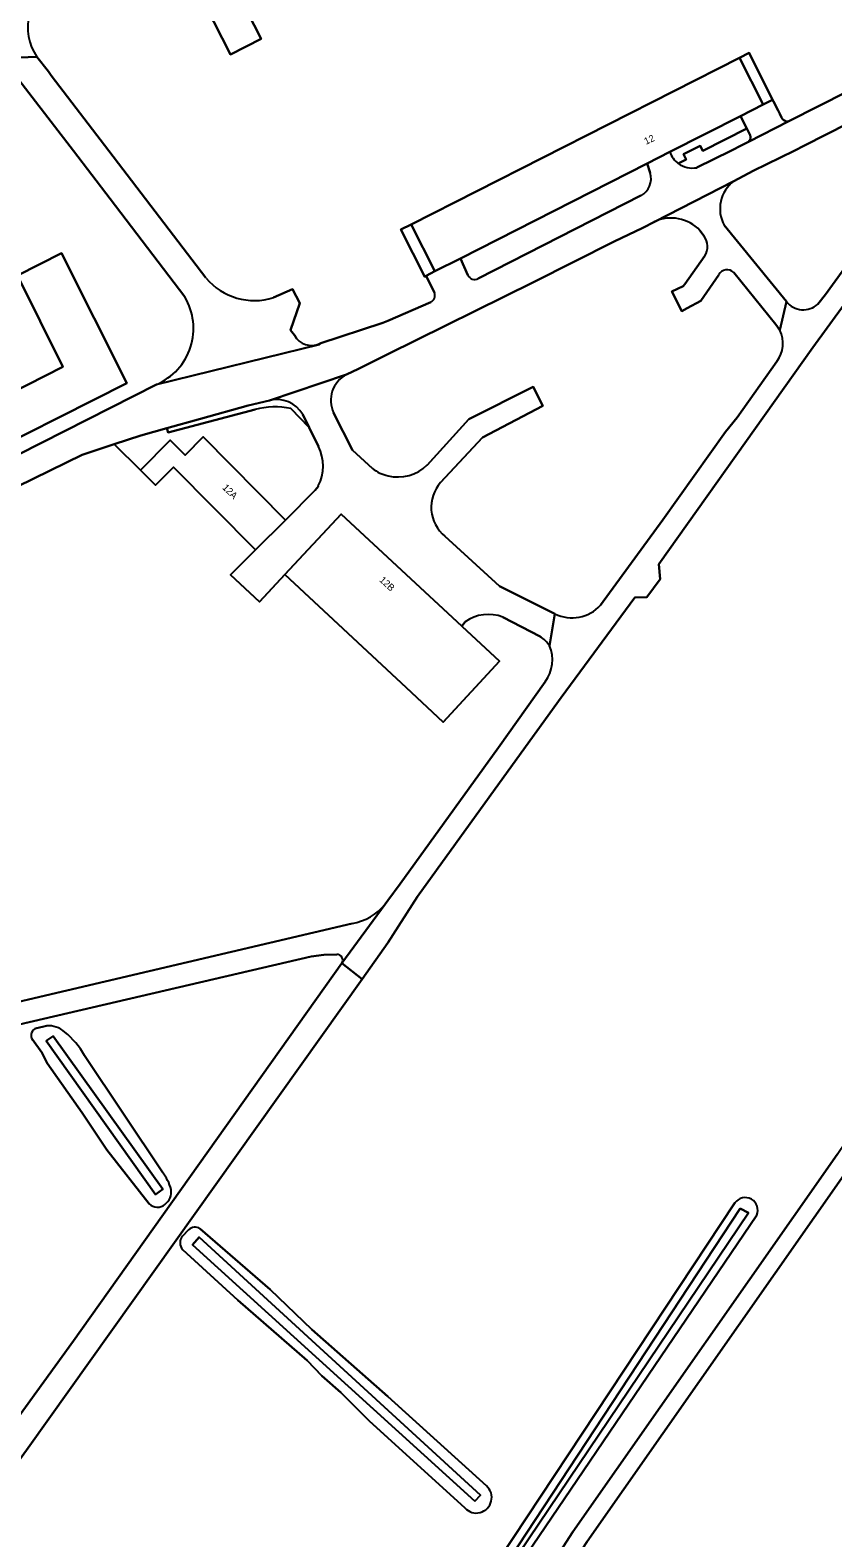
# Model space of a CAD drawing. Extents: x 158132 to 159664, y 385256 to 387218.
# Drawn here: x 158948 to 159064.7, y 386048.5 to 386267.5 of the extents above; entities that cross this region are included whole.
import ezdxf

# ---------------------------------------------------------------- set-up
doc = ezdxf.new("R2010")
doc.units = 0
for name, color, linetype in [('IMGEO_Gemengd_bos', 7, 'Continuous'), ('IMGEO_Grasland_overig', 7, 'Continuous'), ('IMGEO_Groenvoorziening', 7, 'Continuous'), ('IMGEO_Loofbos', 7, 'Continuous'), ('IMGEO_Oever', 7, 'Continuous'), ('IMGEO_Pand', 7, 'Continuous'), ('IMGEO_Pand_nummerreeks', 7, 'Continuous'), ('IMGEO_Rijbaan_lokaal_gesloten', 7, 'Continuous'), ('IMGEO_Rijbaan_lokaal_open', 7, 'Continuous'), ('IMGEO_Voetpad_open', 7, 'Continuous'), ('IMGEO_Waterloop', 7, 'Continuous')]:
    doc.layers.add(name, color=color, linetype=linetype)

msp = doc.modelspace()

# ---------------------------------------------------------------- linework, layer by layer
at = {"layer": 'IMGEO_Gemengd_bos'}
for points in [[(158987.13, 385983.76), (158985.38, 385985.66), (159024.58, 386045.84), (159026.86, 386049.34), (159065.31, 386104.15), (159074.76, 386118.24), (159086.39, 386135.58), (159115.48, 386177.93), (159137.05, 386210.07), (159143.29, 386219.37), (159143.28, 386220.9), (159143.27, 386223.44), (159126.17, 386240.76), (159117.05, 386250), (159112.16, 386254.95), (159110, 386256.99), (159100.09, 386266.87)], [(159081.8, 386262.26), (159076.17, 386258.72), (159060.54, 386250.75), (159059.02, 386250), (159053.08, 386247.07), (159050.25, 386245.6)], [(159062.49, 386227.7), (159063.57, 386229.11), (159071.86, 386240.54), (159078.66, 386250), (159082.37, 386255.16)], [(159048.86, 386239.16), (159057.91, 386228.09)], [(159066.31, 386227.68), (159061.77, 386221.39), (159039.38, 386189.93), (159039.57, 386187.77), (159037.64, 386185.15), (159035.87, 386185.08), (159025.16, 386170.55), (159017.45, 386159.91), (159004.28, 386141.65), (159000, 386134.9), (158996.27, 386129.66), (158947.71, 386061.54), (158903.24, 386000)], [(158980.75, 386192.01), (158968.81, 386204.04), (158966.21, 386201.42), (158964.03, 386203.58), (158960.21, 386207.36), (158955.54, 386205.8), (158946.13, 386201.24), (158935.08, 386195.64), (158931.48, 386193.8)], [(159011.21, 386181.56), (159010.72, 386180.94), (159010.8, 386180.87), (159016.23, 386175.82), (159008.04, 386167), (159002.62, 386172.04), (158985.01, 386188.42), (158981.32, 386184.47), (158977.11, 386188.39), (158980.75, 386192.01)], [(159022.1, 386179.43), (159016.7, 386182.23)], [(158999.61, 386140.55), (159000, 386141.08), (159001.77, 386143.48), (159016.07, 386163.32), (159022.83, 386172.86)], [(158802.75, 386092.98), (158804.95, 386093.18), (158994.79, 386137.73)], [(158797.66, 386086.29), (158812.86, 386069.29), (158886.2, 385981.64), (158898.44, 386000), (158954.3, 386077.08), (158993.31, 386131.95)], [(158992.55, 386133.23), (158990.7, 386133.19), (158988.86, 386132.94), (158847.34, 386100.03), (158802.76, 386090.03)], [(158948.94, 386122.53), (158950.37, 386122.86)], [(158965.3, 386097.01), (158959.16, 386104.84), (158955.56, 386110.22), (158950.46, 386117.42), (158949.67, 386119.01), (158948.31, 386120.86)], [(158955.91, 386118.57), (158967.22, 386101.61)], [(158975.96, 385985.89), (158985.64, 386000), (159000, 386020.95), (159050.43, 386097.13)], [(159053.59, 386095.36), (159021.93, 386048.68), (159014.34, 386037.49), (159000, 386016.65), (158988.53, 386000), (158981.53, 385989.84), (158977.92, 385984.59)], [(158970.12, 386092.32), (158971, 386093.21)], [(158972.7, 386093.39), (158982.89, 386084.58), (158988.94, 386078.73), (159000, 386069), (159014.32, 386056.02)], [(159000, 386063), (158997.26, 386065.5), (158993.13, 386069.59), (158990.37, 386072), (158988.25, 386074.23), (158978.2, 386083.01), (158970.18, 386090.33)], [(159011.17, 386052.84), (159000, 386063)]]:
    msp.add_lwpolyline(points, dxfattribs=at)
for centre, radius, start, end in [((159053.34, 386241.56), 5.08, 127.4877, 208.1683), ((159060.38, 386230.04), 3.15, 218.2687, 312.0282), ((159014.57, 386176.89), 5.75, 68.2733, 125.7069), ((159019.72, 386175.62), 4.49, 33.3189, 58.0708), ((159018.62, 386176.03), 5.27, 323.0521, 22.9275), ((158993.43, 386145.57), 7.96, 279.819, 320.8727), ((158992.59, 386132.39), 0.844, 328.6516, 92.4979), ((158949.21, 386121.47), 1.09, 104.3488, 214.4042), ((158950.66, 386119.32), 3.55, 47.9229, 94.7052), ((158944.6, 386111.9), 13.13, 30.5542, 50.0095), ((158961.61, 386097.25), 7.11, 15.0151, 37.897), ((158966.29, 386098.73), 2.21, 305.4591, 9.459), ((158966.49, 386098.22), 1.7, 225.6124, 310.0133), ((159051.93, 386096.09), 1.82, 336.2967, 145.1548), ((158971.29, 386091.36), 1.51, 140.3052, 222.8547), ((158971.96, 386092.25), 1.36, 57.1738, 135.1287), ((159012.84, 386054.33), 2.24, 221.8777, 48.7556)]:
    msp.add_arc(centre, radius, start, end, dxfattribs=at)
at = {"layer": 'IMGEO_Grasland_overig'}
msp.add_lwpolyline([(159026.34, 386043.95), (159128.6, 385934.11), (159167.77, 385991.84), (159128.38, 386026.44), (159093.47, 386056.67), (159083.99, 386064.99), (159082.8, 386066.54), (159079.43, 386071.09), (159075.57, 386078.05), (159073.99, 386082.33), (159070.33, 386093.52), (159067.29, 386102.62), (159028.94, 386047.93)], close=True, dxfattribs=at)
at = {"layer": 'IMGEO_Groenvoorziening'}
for points in [[(159052.15, 386253.22), (159051.23, 386255.04), (159040.95, 386249.82)], [(159042.19, 386248.16), (159043.32, 386248.74), (159042.94, 386249.48), (159045.38, 386250.72), (159045.76, 386249.98), (159052.15, 386253.22)], [(159038.12, 386246.77), (159037.69, 386248.16), (159010.52, 386234.36), (159011.61, 386231.91)], [(159013.1, 386231.42), (159036.76, 386243.47)]]:
    msp.add_lwpolyline(points, dxfattribs=at)
for centre, radius, start, end in [((159044.27, 386251.01), 3.53, 199.7639, 233.8206), ((159035.43, 386245.94), 2.81, 298.175, 17.0175), ((159012.59, 386232.37), 1.08, 205.2305, 298.594)]:
    msp.add_arc(centre, radius, start, end, dxfattribs=at)
at = {"layer": 'IMGEO_Loofbos'}
for points in [[(159000.7, 386299.06), (158999.99, 386298.66), (158970.44, 386283.97), (158972.59, 386279.64), (158974.3, 386280.51), (158981.55, 386266.24), (158977.09, 386263.98), (158969.84, 386278.24), (158970.61, 386278.64), (158968.45, 386282.98)], [(158954.27, 386250), (158947.82, 386258.43), (158943.93, 386263.45)], [(158948.98, 386263.64), (158950.64, 386261.53), (158951.07, 386260.95), (158959.43, 386250), (158973.55, 386231.51)], [(159006.76, 386229.34), (159005.55, 386231.81), (159005.35, 386231.7), (159001.85, 386238.53), (159003.38, 386239.27), (159051.07, 386263.49), (159052.5, 386264.22), (159055.9, 386257.41), (159056.16, 386256.9), (159056.43, 386256.38), (159056.69, 386255.86), (159056.95, 386255.34), (159057.21, 386254.82), (159057.4, 386254.54), (159057.55, 386254.42), (159057.71, 386254.32), (159057.88, 386254.26), (159058.06, 386254.25), (159058.25, 386254.27), (159075.22, 386262.87)], [(158970.47, 386228.75), (158959.62, 386243.01), (158954.27, 386250)], [(159038.72, 386239.68), (159037.05, 386238.82), (159032.87, 386236.83), (159021.13, 386230.92), (159000, 386220.45), (158995.7, 386218.32), (158993.99, 386217.49)], [(159045.97, 386237.6), (159045.35, 386238.4)], [(159048.08, 386231.99), (159045.49, 386228.19), (159043.49, 386227.13), (159042.71, 386226.68), (159041.26, 386229.54), (159042.89, 386230.31), (159043.16, 386230.59), (159046.06, 386234.72)], [(159056.96, 386223.92), (159056.37, 386224.76), (159050.26, 386232.3)], [(158983.36, 386228.66), (158986.13, 386229.87), (158987.21, 386227.87), (158985.83, 386223.92), (158986.41, 386223.18)], [(158990.08, 386221.99), (158999.26, 386224.98), (159000, 386225.3), (159006.22, 386228.01)], [(159030.9, 386183.96), (159039.93, 386196.38), (159049.07, 386209.14), (159050.73, 386211.25), (159056.52, 386219.38)], [(158894.13, 386179.46), (158912.8, 386188.92), (158966.37, 386216.04)], [(159005.7, 386204.34), (159011.75, 386210.98), (159021.12, 386215.7), (159022.52, 386212.92), (159013.74, 386208.36), (159007.62, 386201.79)], [(158992.1, 386211.91), (158994.84, 386206.51), (158997.75, 386203.82)], [(159008.27, 386193.99), (159016.2, 386186.75), (159024.27, 386182.72)]]:
    msp.add_lwpolyline(points, dxfattribs=at)
msp.add_lwpolyline([(158952.56, 386235.1), (158962.03, 386216.21), (158937.65, 386203.93), (158934.84, 386209.51), (158952.76, 386218.61), (158946.17, 386231.87)], close=True, dxfattribs=at)
for centre, radius, start, end in [((158955.21, 386267.94), 7.57, 117.3529, 214.5917), ((159041.14, 386234.45), 5.77, 43.21, 114.8754), ((159043.8, 386236.09), 2.64, 328.6804, 34.8622), ((159049.28, 386231.31), 1.39, 45.5167, 150.471), ((158980.58, 386237.39), 9.16, 219.9586, 287.696), ((158962.85, 386224.2), 8.88, 293.3649, 30.8479), ((159005.71, 386228.99), 1.11, 297.5174, 18.4207), ((159053.11, 386222), 4.3, 322.41, 26.4889), ((158988.87, 386224.52), 2.8, 208.5385, 295.5691), ((158995.92, 386213.73), 4.23, 117.1543, 205.6072), ((159001.43, 386208.75), 6.15, 233.3194, 256.605), ((159001.42, 386208.73), 6.13, 256.6548, 314.3126), ((159011.73, 386198.21), 5.45, 138.8886, 230.6618), ((159026.75, 386187.8), 5.65, 243.922, 317.2662)]:
    msp.add_arc(centre, radius, start, end, dxfattribs=at)
at = {"layer": 'IMGEO_Oever'}
for points in [[(158950.37, 386122.86), (158948.94, 386122.53)], [(158948.31, 386120.86), (158949.67, 386119.01), (158950.46, 386117.42), (158955.56, 386110.22), (158959.16, 386104.84), (158965.3, 386097.01)], [(158967.22, 386101.61), (158955.91, 386118.57)], [(159050.43, 386097.13), (159000, 386020.95), (158985.64, 386000), (158975.96, 385985.89)], [(158977.92, 385984.59), (158981.53, 385989.84), (158988.53, 386000), (159000, 386016.65), (159014.34, 386037.49), (159021.93, 386048.68), (159053.59, 386095.36)], [(158971, 386093.21), (158970.12, 386092.32)], [(159014.32, 386056.02), (159000, 386069), (158988.94, 386078.73), (158982.89, 386084.58), (158972.7, 386093.39)], [(158970.18, 386090.33), (158978.2, 386083.01), (158988.25, 386074.23), (158990.37, 386072), (158993.13, 386069.59), (158997.26, 386065.5), (159000, 386063), (159011.17, 386052.84)]]:
    msp.add_lwpolyline(points, dxfattribs=at)
for points in [[(158950.33, 386120.68), (158951.34, 386121.34), (158967.29, 386099.14), (158966.21, 386098.36)], [(159051.17, 386096.32), (159052.4, 386095.68), (159005.98, 386026.9), (158978.56, 385986.73), (158977.68, 385985.42), (158977.03, 385985.84), (159015.18, 386041.67)], [(159012.63, 386053.79), (158971.57, 386091.03), (158972.58, 386092.15), (159013.44, 386054.68)]]:
    msp.add_lwpolyline(points, close=True, dxfattribs=at)
for centre, radius, start, end in [((158949.21, 386121.47), 1.09, 104.3488, 214.4042), ((158950.66, 386119.32), 3.55, 47.9229, 94.7052), ((158944.6, 386111.9), 13.13, 30.5542, 50.0095), ((158961.61, 386097.25), 7.11, 15.0151, 37.897), ((158966.29, 386098.73), 2.21, 305.4591, 9.459), ((158966.49, 386098.22), 1.7, 225.6124, 310.0133), ((159051.93, 386096.09), 1.82, 336.2967, 145.1548), ((158971.29, 386091.36), 1.51, 140.3052, 222.8547), ((158971.96, 386092.25), 1.36, 57.1738, 135.1287), ((159012.84, 386054.33), 2.24, 221.8777, 48.7556)]:
    msp.add_arc(centre, radius, start, end, dxfattribs=at)
at = {"layer": 'IMGEO_Pand'}
for points in [[(158977.09, 386263.98), (158981.55, 386266.24), (158974.3, 386280.51), (158972.59, 386279.64), (158970.61, 386278.64), (158969.84, 386278.24)], [(159037.69, 386248.16), (159040.95, 386249.82), (159051.23, 386255.04), (159054.51, 386256.71), (159051.07, 386263.49), (159003.38, 386239.27), (159006.83, 386232.48), (159010.52, 386234.36)], [(158962.03, 386216.21), (158952.56, 386235.1), (158946.17, 386231.87), (158952.76, 386218.61), (158934.84, 386209.51), (158937.65, 386203.93)], [(158980.75, 386192.01), (158985.11, 386196.35), (158973.14, 386208.41), (158970.53, 386205.78), (158968.35, 386207.94), (158964.03, 386203.58), (158966.21, 386201.42), (158968.81, 386204.04)], [(158993.2, 386197.21), (158985.01, 386188.42), (159002.62, 386172.04), (159008.04, 386167), (159016.23, 386175.82), (159010.8, 386180.87), (159010.72, 386180.94)]]:
    msp.add_lwpolyline(points, close=True, dxfattribs=at)
at = {"layer": 'IMGEO_Rijbaan_lokaal_gesloten'}
for points in [[(159089.82, 386265.56), (159082.37, 386255.16), (159078.66, 386250), (159071.86, 386240.54), (159063.57, 386229.11), (159062.49, 386227.7)], [(158943.93, 386263.45), (158948.98, 386263.64)], [(158973.55, 386231.51), (158959.43, 386250), (158951.07, 386260.95), (158950.64, 386261.53), (158948.98, 386263.64), (158943.93, 386263.45), (158947.82, 386258.43), (158954.27, 386250), (158959.62, 386243.01), (158970.47, 386228.75)], [(159075.22, 386262.87), (159058.25, 386254.27), (159052.38, 386251.29), (159051.53, 386250.86), (159049.81, 386250), (159044.88, 386247.54)], [(159021.13, 386230.92), (159032.87, 386236.83), (159037.05, 386238.82), (159038.72, 386239.68), (159050.25, 386245.6), (159053.08, 386247.07), (159059.02, 386250), (159060.54, 386250.75), (159076.17, 386258.72), (159081.8, 386262.26)], [(159022.83, 386172.86), (159016.07, 386163.32), (159001.77, 386143.48), (159000, 386141.08), (158999.61, 386140.55), (158993.31, 386131.95), (158996.27, 386129.66), (159000, 386134.9), (159004.28, 386141.65), (159017.45, 386159.91), (159025.16, 386170.55), (159035.87, 386185.08), (159037.64, 386185.15), (159039.57, 386187.77), (159039.38, 386189.93), (159061.77, 386221.39), (159066.31, 386227.68), (159082.48, 386250)], [(159040.95, 386249.82), (159037.69, 386248.16), (159038.12, 386246.77)], [(159050.25, 386245.6), (159038.72, 386239.68)], [(159036.76, 386243.47), (159013.1, 386231.42)], [(159050.26, 386232.3), (159056.37, 386224.76), (159056.96, 386223.92), (159057.91, 386228.09), (159048.86, 386239.16)], [(159045.35, 386238.4), (159045.97, 386237.6)], [(159011.61, 386231.91), (159010.52, 386234.36), (159006.83, 386232.48), (159005.55, 386231.81), (159006.76, 386229.34)], [(159046.06, 386234.72), (159043.16, 386230.59), (159042.89, 386230.31), (159041.26, 386229.54), (159042.71, 386226.68), (159043.49, 386227.13), (159045.49, 386228.19), (159048.08, 386231.99)], [(158931.48, 386193.8), (158935.08, 386195.64), (158946.13, 386201.24), (158955.54, 386205.8), (158960.21, 386207.36), (158964.07, 386208.65), (158967.86, 386209.71), (158972.74, 386211.07), (158979.68, 386212.97), (158982.77, 386213.7), (158993.99, 386217.49), (158995.7, 386218.32), (159000, 386220.45), (159021.13, 386230.92)], [(158986.41, 386223.18), (158985.83, 386223.92), (158987.21, 386227.87), (158986.13, 386229.87), (158983.36, 386228.66)], [(159006.22, 386228.01), (159000, 386225.3), (158999.26, 386224.98), (158990.08, 386221.99), (158990.05, 386221.86), (158966.37, 386216.04), (158912.8, 386188.92), (158894.13, 386179.46)], [(159057.91, 386228.09), (159056.96, 386223.92)], [(158966.37, 386216.04), (158990.05, 386221.86), (158990.08, 386221.99)], [(159056.52, 386219.38), (159050.73, 386211.25), (159049.07, 386209.14), (159039.93, 386196.38), (159030.9, 386183.96)], [(158993.99, 386217.49), (158982.77, 386213.7)], [(159013.74, 386208.36), (159022.52, 386212.92), (159021.12, 386215.7), (159011.75, 386210.98), (159005.7, 386204.34)], [(158987.62, 386211.66), (158988.54, 386209.81), (158989.92, 386207.03)], [(158997.75, 386203.82), (158994.84, 386206.51), (158992.1, 386211.91)], [(159007.62, 386201.79), (159013.74, 386208.36)], [(158989.88, 386201.29), (158989.42, 386200.68), (158985.11, 386196.35), (158980.75, 386192.01), (158977.11, 386188.39), (158981.32, 386184.47), (158985.01, 386188.42), (158993.2, 386197.21), (159010.72, 386180.94), (159011.21, 386181.56)], [(159023.48, 386178.08), (159024.27, 386182.72), (159016.2, 386186.75), (159008.27, 386193.99)], [(159016.7, 386182.23), (159022.1, 386179.43)], [(159024.27, 386182.72), (159023.48, 386178.08)], [(158993.31, 386131.95), (158999.61, 386140.55)], [(158994.79, 386137.73), (158804.95, 386093.18), (158802.75, 386092.98)], [(158847.34, 386100.03), (158988.86, 386132.94), (158990.7, 386133.19), (158992.55, 386133.23)], [(158903.24, 386000), (158947.71, 386061.54), (158996.27, 386129.66), (158993.31, 386131.95), (158954.3, 386077.08), (158898.44, 386000)]]:
    msp.add_lwpolyline(points, dxfattribs=at)
for centre, radius, start, end in [((158955.21, 386267.94), 7.57, 117.3529, 214.5917), ((159044.27, 386251.01), 3.53, 199.7639, 233.8206), ((159044.27, 386251.01), 3.53, 233.816, 280.018), ((159035.43, 386245.94), 2.81, 298.175, 17.0175), ((159053.34, 386241.56), 5.08, 127.4877, 208.1683), ((159041.14, 386234.45), 5.77, 43.21, 114.8754), ((159043.8, 386236.09), 2.64, 328.6804, 34.8622), ((159049.28, 386231.31), 1.39, 45.5167, 150.471), ((158980.58, 386237.39), 9.16, 219.9586, 287.696), ((159012.59, 386232.37), 1.08, 205.2305, 298.594), ((158962.85, 386224.2), 8.88, 293.3649, 30.8479), ((159005.71, 386228.99), 1.11, 297.5174, 18.4207), ((159060.38, 386230.04), 3.15, 218.2687, 312.0282), ((159053.11, 386222), 4.3, 322.41, 26.4889), ((158988.87, 386224.52), 2.8, 208.5385, 295.5691), ((158995.92, 386213.73), 4.23, 117.1543, 205.6072), ((158983.87, 386209.54), 4.31, 29.5115, 104.7747), ((158984, 386204.21), 6.56, 333.5855, 25.497), ((159001.43, 386208.75), 6.15, 233.3194, 256.605), ((159001.42, 386208.73), 6.13, 256.6548, 314.3126), ((159011.73, 386198.21), 5.45, 138.8886, 230.6618), ((159026.75, 386187.8), 5.65, 243.922, 317.2662), ((159014.57, 386176.89), 5.75, 68.2733, 125.7069), ((159019.72, 386175.62), 4.49, 33.3189, 58.0708), ((159018.62, 386176.03), 5.27, 323.0521, 22.9275), ((158993.43, 386145.57), 7.96, 279.819, 320.8727), ((158992.59, 386132.39), 0.844, 328.6516, 92.4979)]:
    msp.add_arc(centre, radius, start, end, dxfattribs=at)
at = {"layer": 'IMGEO_Rijbaan_lokaal_open'}
msp.add_lwpolyline([(159058.25, 386254.27), (159058.06, 386254.25), (159057.88, 386254.26), (159057.71, 386254.32), (159057.55, 386254.42), (159057.4, 386254.54), (159057.21, 386254.82), (159056.95, 386255.34), (159056.69, 386255.86), (159056.43, 386256.38), (159056.16, 386256.9), (159055.9, 386257.41), (159054.51, 386256.71), (159051.23, 386255.04), (159052.15, 386253.22), (159052.64, 386252.25), (159052.67, 386252.04), (159052.67, 386251.82), (159052.62, 386251.64), (159052.52, 386251.45), (159052.38, 386251.29)], close=True, dxfattribs=at)
for points in [[(158982.77, 386213.7), (158979.68, 386212.97), (158972.74, 386211.07), (158967.86, 386209.71), (158968.04, 386209.05), (158980.69, 386212.4)], [(158985.88, 386212.53), (158988.54, 386209.81), (158987.62, 386211.66)]]:
    msp.add_lwpolyline(points, dxfattribs=at)
for centre, radius, start, end in [((158983.56, 386201.66), 11.12, 77.9682, 104.9689), ((158983.87, 386209.54), 4.31, 29.5115, 104.7747)]:
    msp.add_arc(centre, radius, start, end, dxfattribs=at)
at = {"layer": 'IMGEO_Voetpad_open'}
for points in [[(159054.51, 386256.71), (159055.9, 386257.41), (159052.5, 386264.22), (159051.07, 386263.49)], [(159003.38, 386239.27), (159001.85, 386238.53), (159005.35, 386231.7), (159005.55, 386231.81), (159006.83, 386232.48)]]:
    msp.add_lwpolyline(points, close=True, dxfattribs=at)
for points in [[(159052.38, 386251.29), (159052.52, 386251.45), (159052.62, 386251.64), (159052.67, 386251.82), (159052.67, 386252.04), (159052.64, 386252.25), (159052.15, 386253.22), (159045.76, 386249.98), (159045.38, 386250.72), (159042.94, 386249.48), (159043.32, 386248.74), (159042.19, 386248.16)], [(159044.88, 386247.54), (159049.81, 386250), (159051.53, 386250.86), (159052.38, 386251.29)], [(158980.69, 386212.4), (158968.04, 386209.05), (158967.86, 386209.71), (158964.07, 386208.65), (158960.21, 386207.36), (158964.03, 386203.58), (158968.35, 386207.94), (158970.53, 386205.78), (158973.14, 386208.41), (158985.11, 386196.35), (158989.42, 386200.68), (158989.88, 386201.29)], [(158988.54, 386209.81), (158985.88, 386212.53)], [(158989.92, 386207.03), (158988.54, 386209.81)], [(159065.31, 386104.15), (159026.86, 386049.34), (159024.58, 386045.84), (158985.38, 385985.66), (158987.13, 385983.76), (159026.34, 386043.95), (159028.94, 386047.93), (159067.29, 386102.62)]]:
    msp.add_lwpolyline(points, dxfattribs=at)
for centre, radius, start, end in [((159044.27, 386251.01), 3.53, 233.816, 280.018), ((158983.56, 386201.66), 11.12, 77.9682, 104.9689), ((158984, 386204.21), 6.56, 333.5855, 25.497)]:
    msp.add_arc(centre, radius, start, end, dxfattribs=at)
at = {"layer": 'IMGEO_Waterloop'}
for points in [[(158950.33, 386120.68), (158966.21, 386098.36), (158967.29, 386099.14), (158951.34, 386121.34)], [(159051.17, 386096.32), (159015.18, 386041.67), (158977.03, 385985.84), (158977.68, 385985.42), (158978.56, 385986.73), (159005.98, 386026.9), (159052.4, 386095.68)], [(159012.63, 386053.79), (159013.44, 386054.68), (158972.58, 386092.15), (158971.57, 386091.03)]]:
    msp.add_lwpolyline(points, close=True, dxfattribs=at)

# ---------------------------------------------------------------- texts
at = {"layer": 'IMGEO_Pand_nummerreeks'}
for s, rotation, p in [('12', 25.1815, (159037.51, 386250.85)), ('12A', 315.3647, (158975.85, 386200.97)), ('12B', 316.9766, (158998.67, 386187.53))]:
    msp.add_text(s, height=1, rotation=rotation, dxfattribs=at).set_placement(p)

doc.saveas('drawing.dxf')
